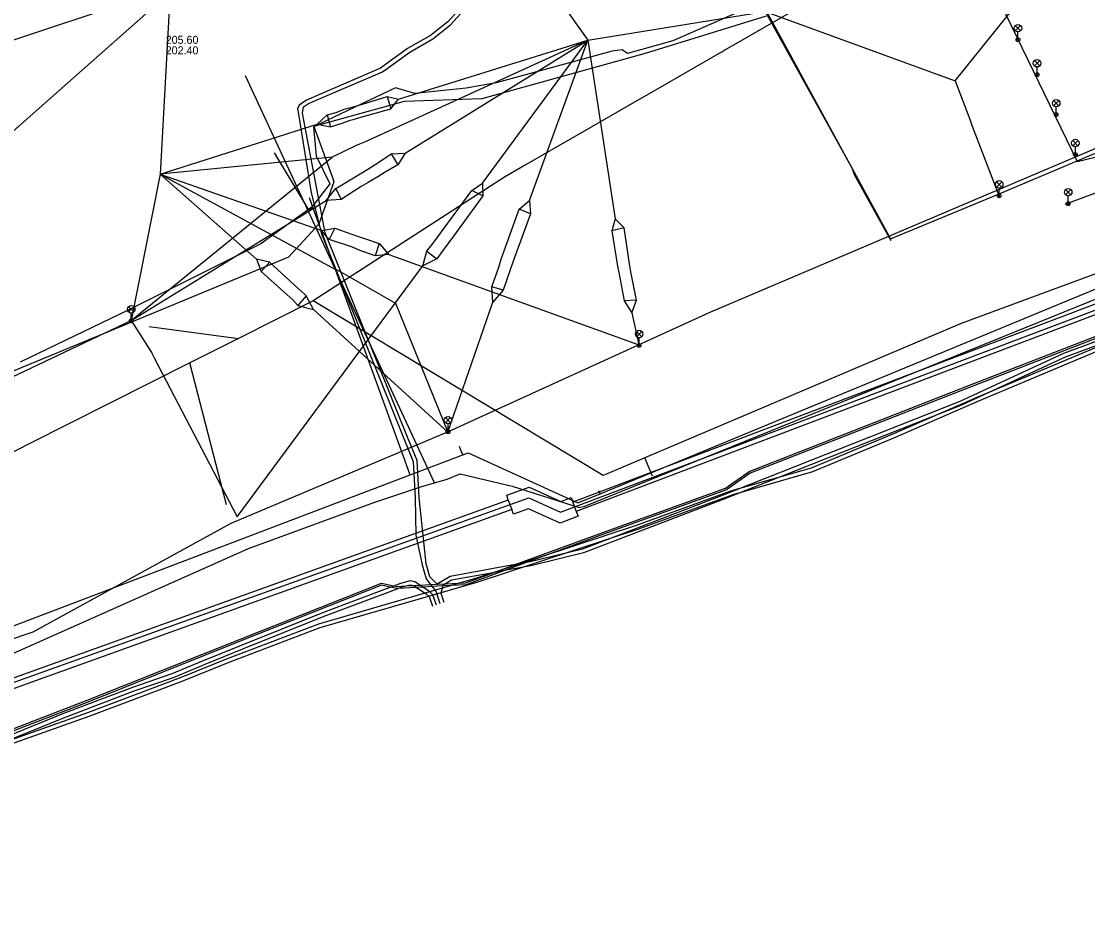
# Model space of a CAD drawing. Extents: x -596228 to -595156, y -1161235 to -1159373.
# Drawn here: x -595672.5 to -595565.9, y -1160372.3 to -1160281.7 of the extents above; entities that cross this region are included whole.
import ezdxf

# ---------------------------------------------------------------- set-up
doc = ezdxf.new("R2010")
doc.units = 0
for name, color, linetype in [('Vrstva 1', 7, 'Continuous'), ('Vrstva 10', 7, 'Continuous'), ('Vrstva 12', 7, 'Continuous'), ('Vrstva 14', 7, 'Continuous'), ('Vrstva 16', 7, 'Continuous'), ('Vrstva 33', 7, 'Continuous'), ('Vrstva 42', 7, 'Continuous'), ('Vrstva 44', 7, 'Continuous'), ('Vrstva 54', 7, 'Continuous'), ('Vrstva 55', 7, 'Continuous'), ('Vrstva 9', 7, 'Continuous')]:
    doc.layers.add(name, color=color, linetype=linetype)

msp = doc.modelspace()

# ---------------------------------------------------------------- linework, layer by layer
at = {"layer": 'Vrstva 1'}
for p, q in [((-595659.743, -1160312.174), (-595650.824, -1160313.363)), ((-595652.016, -1160330.002), (-595655.67, -1160315.804))]:
    msp.add_line(p, q, dxfattribs=at)
at = {"layer": 'Vrstva 10'}
for p, q in [((-595556.13, -1160306.5), (-595617.39, -1160329.73)), ((-595556.13, -1160306.5), (-595617.39, -1160329.73)), ((-595555.81, -1160307.45), (-595617.04, -1160330.67)), ((-595555.81, -1160307.45), (-595617.04, -1160330.67)), ((-595623.84, -1160329.51), (-595690.16, -1160353.38)), ((-595623.84, -1160329.51), (-595690.16, -1160353.38)), ((-595623.84, -1160329.51), (-595623.5, -1160330.45)), ((-595623.84, -1160329.51), (-595623.5, -1160330.45)), ((-595617.39, -1160329.73), (-595617.04, -1160330.67)), ((-595617.39, -1160329.73), (-595617.04, -1160330.67)), ((-595623.5, -1160330.45), (-595689.9, -1160354.35)), ((-595623.5, -1160330.45), (-595689.9, -1160354.35))]:
    msp.add_line(p, q, dxfattribs=at)
for points in [[(-595623.84, -1160329.51), (-595624, -1160329.04), (-595621.74, -1160328.23), (-595618.58, -1160329.65), (-595617.57, -1160329.26), (-595617.39, -1160329.73)], [(-595623.84, -1160329.51), (-595624, -1160329.04), (-595621.74, -1160328.23), (-595618.58, -1160329.65), (-595617.57, -1160329.26), (-595617.39, -1160329.73)], [(-595617.04, -1160330.67), (-595616.86, -1160331.13), (-595618.65, -1160331.81), (-595621.82, -1160330.38), (-595623.33, -1160330.92), (-595623.5, -1160330.45)], [(-595617.04, -1160330.67), (-595616.86, -1160331.13), (-595618.65, -1160331.81), (-595621.82, -1160330.38), (-595623.33, -1160330.92), (-595623.5, -1160330.45)]]:
    msp.add_lwpolyline(points, dxfattribs=at)
at = {"layer": 'Vrstva 12'}
msp.add_lwpolyline([(-595733.28, -1160359.44), (-595691.96, -1160354.4), (-595622.73, -1160329.64), (-595621.78, -1160329.3), (-595618.62, -1160330.73), (-595554.08, -1160306.33)], dxfattribs=at)
at = {"layer": 'Vrstva 14'}
for p, q in [((-595633.652, -1160327.007), (-595628.395, -1160325.007)), ((-595628.516, -1160324.69), (-595628.716, -1160324.165)), ((-595628.395, -1160325.007), (-595628.516, -1160324.69)), ((-595633.652, -1160327.007), (-595633.714, -1160326.844)), ((-595614.67, -1160328.883), (-595614.788, -1160328.598))]:
    msp.add_line(p, q, dxfattribs=at)
for points in [[(-595643.344, -1160300.351), (-595643.571, -1160300.434), (-595643.778, -1160300.509), (-595647.213, -1160294.815)], [(-595614.67, -1160328.883), (-595547.051, -1160300.94), (-595538.035, -1160297.214), (-595529.442, -1160294.26)], [(-595633.714, -1160326.844), (-595633.856, -1160326.471), (-595634.328, -1160325.169), (-595643.344, -1160300.351), (-595643.725, -1160299.302)], [(-595628.395, -1160325.007), (-595627.869, -1160324.806), (-595616.876, -1160329.795), (-595614.67, -1160328.883)], [(-595749.15, -1160356.25), (-595745.334, -1160357.016), (-595740.305, -1160357.959), (-595721.901, -1160355.127), (-595697.852, -1160351.426), (-595690.937, -1160348.796), (-595633.652, -1160327.007)]]:
    msp.add_lwpolyline(points, dxfattribs=at)
at = {"layer": 'Vrstva 16'}
msp.add_line((-595631.22, -1160327.8), (-595650.11, -1160287.1), dxfattribs=at)
msp.add_lwpolyline([(-595846.15, -1160336.98), (-595838.77, -1160338.11), (-595833.73, -1160339.33), (-595822.21, -1160341.41), (-595795.62, -1160345.96), (-595752.4, -1160353.65), (-595705.45, -1160352.2), (-595699.2, -1160353.46), (-595687.59, -1160351.18), (-595687.183, -1160350.999), (-595649.82, -1160334.37), (-595637.18, -1160329.71), (-595632.58, -1160328.19), (-595631.22, -1160327.8), (-595629.94, -1160327.43), (-595628.67, -1160326.89), (-595623.45, -1160328.11), (-595616.75, -1160330.26), (-595616.2, -1160330.11), (-595541.13, -1160299.69), (-595536.93, -1160298.59)], dxfattribs=at)
at = {"layer": 'Vrstva 33'}
for p, q in [((-595573.155, -1160282.085), (-595572.625, -1160282.615)), ((-595573.155, -1160282.615), (-595572.625, -1160282.085)), ((-595572.89, -1160283.5), (-595572.89, -1160282.725)), ((-595571.245, -1160285.585), (-595570.715, -1160286.115)), ((-595571.245, -1160286.115), (-595570.715, -1160285.585)), ((-595570.98, -1160287), (-595570.98, -1160286.225)), ((-595569.325, -1160289.575), (-595568.795, -1160290.105)), ((-595569.325, -1160290.105), (-595568.795, -1160289.575)), ((-595569.06, -1160290.99), (-595569.06, -1160290.215)), ((-595567.415, -1160293.565), (-595566.885, -1160294.095)), ((-595567.415, -1160294.095), (-595566.885, -1160293.565)), ((-595567.15, -1160294.98), (-595567.15, -1160294.205)), ((-595575.025, -1160297.695), (-595574.495, -1160298.225)), ((-595575.025, -1160298.225), (-595574.495, -1160297.695)), ((-595574.76, -1160299.11), (-595574.76, -1160298.335)), ((-595568.125, -1160298.475), (-595567.595, -1160299.005)), ((-595568.125, -1160299.005), (-595567.595, -1160298.475)), ((-595567.86, -1160299.89), (-595567.86, -1160299.115)), ((-595661.805, -1160310.185), (-595661.275, -1160310.715)), ((-595661.805, -1160310.715), (-595661.275, -1160310.185)), ((-595661.54, -1160311.6), (-595661.54, -1160310.825)), ((-595611.025, -1160312.655), (-595610.495, -1160313.185)), ((-595611.025, -1160313.185), (-595610.495, -1160312.655)), ((-595610.76, -1160314.07), (-595610.76, -1160313.295)), ((-595630.135, -1160321.265), (-595629.605, -1160321.795)), ((-595630.135, -1160321.795), (-595629.605, -1160321.265)), ((-595629.87, -1160322.68), (-595629.87, -1160321.905))]:
    msp.add_line(p, q, dxfattribs=at)
for centre, radius in [((-595572.89, -1160282.35), 0.375), ((-595572.89, -1160283.5), 0.19), ((-595572.89, -1160283.5), 0.05), ((-595570.98, -1160285.85), 0.375), ((-595570.98, -1160287), 0.19), ((-595570.98, -1160287), 0.05), ((-595569.06, -1160289.84), 0.375), ((-595569.06, -1160290.99), 0.19), ((-595569.06, -1160290.99), 0.05), ((-595567.15, -1160293.83), 0.375), ((-595567.15, -1160294.98), 0.19), ((-595567.15, -1160294.98), 0.05), ((-595574.76, -1160297.96), 0.375), ((-595567.86, -1160298.74), 0.375), ((-595574.76, -1160299.11), 0.19), ((-595574.76, -1160299.11), 0.05), ((-595567.86, -1160299.89), 0.19), ((-595567.86, -1160299.89), 0.05), ((-595661.54, -1160310.45), 0.375), ((-595661.54, -1160311.6), 0.19), ((-595661.54, -1160311.6), 0.05), ((-595610.76, -1160312.92), 0.375), ((-595610.76, -1160314.07), 0.19), ((-595610.76, -1160314.07), 0.05), ((-595629.87, -1160321.53), 0.375), ((-595629.87, -1160322.68), 0.19), ((-595629.87, -1160322.68), 0.05)]:
    msp.add_circle(centre, radius, dxfattribs=at)
at = {"layer": 'Vrstva 42'}
for points in [[(-595564.53, -1160268.19), (-595566.79, -1160270.52), (-595571.2, -1160272.79), (-595583.54, -1160277.43), (-595586.61, -1160277.56), (-595590.82, -1160278.37), (-595594.37, -1160278.59), (-595597.88, -1160279.42), (-595607.38, -1160283.62), (-595611.94, -1160284.88), (-595612.46, -1160284.51), (-595613.45, -1160284.64), (-595625.04, -1160287.81), (-595628.07, -1160288.33), (-595633.2, -1160288.88), (-595635.11, -1160288.31), (-595643.31, -1160292.2), (-595643.06, -1160295.12), (-595641.7, -1160297.92), (-595643.5, -1160300.23), (-595648.58, -1160303.89), (-595661.84, -1160310.55), (-595672.63, -1160315.73)], [(-595564.53, -1160268.19), (-595566.79, -1160270.52), (-595571.2, -1160272.79), (-595583.54, -1160277.43), (-595586.61, -1160277.56), (-595590.82, -1160278.37), (-595594.37, -1160278.59), (-595597.88, -1160279.42), (-595607.38, -1160283.62), (-595611.94, -1160284.88), (-595612.46, -1160284.51), (-595613.45, -1160284.64), (-595625.04, -1160287.81), (-595628.07, -1160288.33), (-595633.2, -1160288.88), (-595635.11, -1160288.31), (-595643.31, -1160292.2), (-595643.06, -1160295.12), (-595641.7, -1160297.92), (-595643.5, -1160300.23), (-595648.58, -1160303.89), (-595661.84, -1160310.55), (-595672.63, -1160315.73)], [(-595564.53, -1160268.19), (-595566.79, -1160270.52), (-595571.2, -1160272.79), (-595583.54, -1160277.43), (-595586.61, -1160277.56), (-595590.82, -1160278.37), (-595594.37, -1160278.59), (-595597.88, -1160279.42), (-595607.38, -1160283.62), (-595611.94, -1160284.88), (-595612.46, -1160284.51), (-595613.45, -1160284.64), (-595625.04, -1160287.81), (-595628.07, -1160288.33), (-595633.2, -1160288.88), (-595635.11, -1160288.31), (-595643.31, -1160292.2), (-595643.06, -1160295.12), (-595641.7, -1160297.92), (-595643.5, -1160300.23), (-595648.58, -1160303.89), (-595661.84, -1160310.55), (-595672.63, -1160315.73)], [(-595564.53, -1160268.19), (-595566.79, -1160270.52), (-595571.2, -1160272.79), (-595583.54, -1160277.43), (-595586.61, -1160277.56), (-595590.82, -1160278.37), (-595594.37, -1160278.59), (-595597.88, -1160279.42), (-595607.38, -1160283.62), (-595611.94, -1160284.88), (-595612.46, -1160284.51), (-595613.45, -1160284.64), (-595625.04, -1160287.81), (-595628.07, -1160288.33), (-595633.2, -1160288.88), (-595635.11, -1160288.31), (-595643.31, -1160292.2), (-595643.06, -1160295.12), (-595641.7, -1160297.92), (-595643.5, -1160300.23), (-595648.58, -1160303.89), (-595661.84, -1160310.55), (-595672.63, -1160315.73)], [(-595628.123, -1160279.792), (-595629.888, -1160281.721), (-595631.624, -1160283.069), (-595633.919, -1160284.394), (-595636.628, -1160286.352), (-595644.008, -1160289.527), (-595644.76, -1160290.027), (-595644.918, -1160290.395), (-595644.818, -1160290.936), (-595643.539, -1160298.801), (-595642.524, -1160302.908), (-595634.288, -1160323.372), (-595633.365, -1160325.656), (-595633.164, -1160329.297), (-595633.071, -1160333.02), (-595632.45, -1160335.99), (-595632.04, -1160337.396), (-595631.608, -1160337.969), (-595631.463, -1160338.162), (-595631.097, -1160338.647), (-595631.067, -1160338.697), (-595630.673, -1160339.855)], [(-595561.987, -1160312.519), (-595568.319, -1160314.864), (-595578.686, -1160319.652), (-595602.622, -1160329.131), (-595616.428, -1160334.42), (-595621.668, -1160335.701), (-595622.024, -1160335.765), (-595623.167, -1160335.973), (-595629.66, -1160337.15), (-595630.966, -1160337.929), (-595631.68, -1160337.204), (-595632.06, -1160335.902), (-595632.764, -1160329.273), (-595632.969, -1160325.568), (-595633.918, -1160323.222), (-595642.14, -1160302.788), (-595644.414, -1160290.839), (-595644.302, -1160290.222), (-595643.812, -1160289.877), (-595636.43, -1160286.702), (-595633.701, -1160284.73), (-595631.4, -1160283.401), (-595629.616, -1160282.015), (-595627.915, -1160280.15)], [(-595598.08, -1160280.55), (-595585.62, -1160303.42), (-595574.78, -1160298.9), (-595556.39, -1160291.15), (-595536.54, -1160296.17), (-595511.97, -1160292.34)], [(-595678.894, -1160354.516), (-595665.947, -1160349.527), (-595650.707, -1160343.437), (-595636.529, -1160337.816), (-595635.296, -1160338.081), (-595634.982, -1160338.149), (-595634.099, -1160338.102), (-595633.34, -1160338.061), (-595632.642, -1160338.024), (-595631.608, -1160337.969), (-595630.12, -1160337.889), (-595628.09, -1160337.781), (-595625.353, -1160336.776), (-595623.167, -1160335.973), (-595614.764, -1160332.886), (-595602.117, -1160328.311), (-595599.768, -1160326.651), (-595577.906, -1160318.107), (-595563.975, -1160312.716)], [(-595563.905, -1160312.904), (-595577.834, -1160318.293), (-595599.672, -1160326.829), (-595602.023, -1160328.489), (-595614.696, -1160333.074), (-595622.024, -1160335.765), (-595624.211, -1160336.569), (-595628.05, -1160337.979), (-595630.401, -1160338.105), (-595631.463, -1160338.162), (-595632.356, -1160338.21), (-595633.034, -1160338.246), (-595634.857, -1160338.343), (-595634.998, -1160338.351), (-595635.642, -1160338.212), (-595636.511, -1160338.024), (-595650.633, -1160343.623), (-595665.873, -1160349.713), (-595678.826, -1160354.704)], [(-595561.845, -1160312.893), (-595568.165, -1160315.234), (-595578.528, -1160320.02), (-595602.476, -1160329.503), (-595616.308, -1160334.802), (-595621.584, -1160336.093), (-595624.211, -1160336.569), (-595625.353, -1160336.776), (-595629.518, -1160337.53), (-595630.12, -1160337.889), (-595630.386, -1160338.048), (-595630.401, -1160338.105), (-595630.598, -1160338.837), (-595630.295, -1160339.726)], [(-595676.303, -1160354.082), (-595668.266, -1160350.83), (-595661.388, -1160348.207), (-595657.459, -1160346.867), (-595654.307, -1160345.565), (-595650.529, -1160344.009), (-595642.394, -1160340.755), (-595635.642, -1160338.212), (-595635.296, -1160338.081), (-595634.575, -1160337.81), (-595633.622, -1160337.568), (-595633.135, -1160337.704), (-595632.642, -1160338.024), (-595632.356, -1160338.21), (-595631.809, -1160338.565), (-595631.408, -1160338.939), (-595631.052, -1160339.985)], [(-595684.368, -1160360.824), (-595684.917, -1160360.681), (-595685.413, -1160360.091), (-595685.972, -1160358.576), (-595685.818, -1160358.132), (-595683.778, -1160357.346), (-595676.157, -1160354.454), (-595668.12, -1160351.202), (-595661.252, -1160348.583), (-595657.317, -1160347.241), (-595654.155, -1160345.935), (-595650.379, -1160344.379), (-595642.25, -1160341.127), (-595634.857, -1160338.343), (-595634.455, -1160338.192), (-595634.099, -1160338.102), (-595633.626, -1160337.982), (-595633.34, -1160338.061), (-595633.301, -1160338.072), (-595633.034, -1160338.246), (-595632.057, -1160338.881), (-595631.753, -1160339.163), (-595631.429, -1160340.113)]]:
    msp.add_lwpolyline(points, dxfattribs=at)
at = {"layer": 'Vrstva 44'}
for points in [[(-595717.364, -1160360.106), (-595716.77, -1160359.938), (-595712.271, -1160360.888), (-595708.136, -1160362.092), (-595704.554, -1160363.181), (-595701.491, -1160363.274), (-595693.888, -1160361.725), (-595687.262, -1160359.141), (-595675.243, -1160354.482), (-595665.747, -1160351.12), (-595656.455, -1160347.611), (-595651.761, -1160345.734), (-595642.65, -1160342.268), (-595626.862, -1160337.683), (-595610.795, -1160332.384), (-595601.354, -1160328.949), (-595593.41, -1160326.668), (-595585.132, -1160323.221), (-595576.808, -1160319.609), (-595564.888, -1160314.602), (-595558.278, -1160311.976), (-595541.589, -1160305.764), (-595540.697, -1160305.102), (-595540.254, -1160304.773)], [(-595717.89, -1160359.792), (-595716.784, -1160359.526), (-595712.174, -1160360.5), (-595708.022, -1160361.709), (-595704.489, -1160362.783), (-595701.525, -1160362.873), (-595694.001, -1160361.34), (-595687.407, -1160358.768), (-595675.382, -1160354.107), (-595665.884, -1160350.744), (-595656.6, -1160347.238), (-595651.906, -1160345.361), (-595642.777, -1160341.888), (-595626.98, -1160337.301), (-595610.926, -1160332.006), (-595601.478, -1160328.568), (-595593.543, -1160326.29), (-595585.289, -1160322.853), (-595576.965, -1160319.241), (-595565.039, -1160314.232)]]:
    msp.add_lwpolyline(points, dxfattribs=at)
at = {"layer": 'Vrstva 54'}
for p, q in [((-595627.289, -1160267.424), (-595615.875, -1160283.555)), ((-595579.158, -1160287.602), (-595564.055, -1160268.793)), ((-595681.72, -1160286.32), (-595657.64, -1160278.29)), ((-595657.64, -1160278.29), (-595658.64, -1160296.948)), ((-595615.875, -1160283.555), (-595598.145, -1160280.664)), ((-595598.145, -1160280.664), (-595579.158, -1160287.602)), ((-595635.949, -1160289.176), (-595635.569, -1160290.396)), ((-595641.944, -1160291.002), (-595641.632, -1160292.219)), ((-595661.531, -1160311.558), (-595641.459, -1160295.235)), ((-595635.536, -1160294.917), (-595634.873, -1160296.002)), ((-595658.64, -1160296.948), (-595661.531, -1160311.558)), ((-595641.096, -1160298.359), (-595640.553, -1160299.48)), ((-595626.4, -1160299.101), (-595627.503, -1160298.568)), ((-595621.626, -1160300.905), (-595622.759, -1160300.444)), ((-595641.17, -1160302.34), (-595641.752, -1160303.47)), ((-595612.27, -1160302.297), (-595613.504, -1160302.617)), ((-595636.755, -1160303.883), (-595637.151, -1160305.109)), ((-595631.973, -1160304.645), (-595630.981, -1160305.407)), ((-595647.73, -1160305.75), (-595648.548, -1160306.664)), ((-595644.045, -1160309.106), (-595644.878, -1160310.052)), ((-595624.348, -1160308.542), (-595625.493, -1160308.215)), ((-595611.008, -1160309.527), (-595612.247, -1160309.602))]:
    msp.add_line(p, q, dxfattribs=at)
for points in [[(-595598.145, -1160280.664), (-595589.47, -1160296.36), (-595589.253, -1160296.957), (-595585.589, -1160303.568)], [(-595661.531, -1160311.558), (-595642.046, -1160299.563), (-595641.096, -1160298.359), (-595638.498, -1160296.807), (-595637.879, -1160296.44), (-595637.508, -1160296.195), (-595636.887, -1160295.794), (-595635.536, -1160294.917), (-595634.153, -1160294.825), (-595615.875, -1160283.555)], [(-595658.64, -1160296.948), (-595642.959, -1160291.942), (-595641.944, -1160291.002), (-595641.066, -1160290.76), (-595640.254, -1160290.426), (-595639.597, -1160290.279), (-595638.848, -1160290.087), (-595635.949, -1160289.176), (-595634.835, -1160289.452), (-595615.875, -1160283.555)], [(-595615.875, -1160283.555), (-595638.223, -1160293.727), (-595639.036, -1160294.082), (-595641.459, -1160295.235), (-595658.64, -1160296.948)], [(-595650.954, -1160331.19), (-595632.393, -1160306.087), (-595631.973, -1160304.645), (-595631.144, -1160303.56), (-595630.633, -1160302.827), (-595627.503, -1160298.568), (-595626.406, -1160297.824), (-595615.875, -1160283.555)], [(-595629.876, -1160322.744), (-595625.378, -1160309.719), (-595625.493, -1160308.215), (-595624.778, -1160306.252), (-595624.542, -1160305.446), (-595622.759, -1160300.444), (-595621.726, -1160299.585), (-595615.875, -1160283.555)], [(-595615.875, -1160283.555), (-595613.16, -1160301.397), (-595613.504, -1160302.617), (-595612.909, -1160306.143), (-595612.757, -1160306.934), (-595612.247, -1160309.602), (-595611.482, -1160310.792), (-595610.777, -1160313.993)], [(-595579.158, -1160287.602), (-595577.662, -1160291.528), (-595577.45, -1160292.135), (-595574.784, -1160299.079)], [(-595642.959, -1160291.942), (-595641.632, -1160292.219), (-595640.455, -1160291.83), (-595639.635, -1160291.549), (-595639.367, -1160291.467), (-595638.581, -1160291.233), (-595635.569, -1160290.396), (-595634.835, -1160289.452)], [(-595634.153, -1160294.825), (-595634.873, -1160296.002), (-595636.167, -1160296.733), (-595636.873, -1160297.195), (-595637.86, -1160297.763), (-595638.547, -1160298.187), (-595640.553, -1160299.48), (-595642.046, -1160299.563)], [(-595658.64, -1160296.948), (-595642.508, -1160302.561), (-595641.17, -1160302.34), (-595638.906, -1160303.146), (-595638.107, -1160303.404), (-595636.755, -1160303.883), (-595635.781, -1160304.955), (-595610.777, -1160313.993)], [(-595658.64, -1160296.948), (-595641.48, -1160306.275), (-595640.733, -1160306.639), (-595635.131, -1160309.848), (-595629.876, -1160322.744)], [(-595629.876, -1160322.744), (-595643.306, -1160310.464), (-595644.045, -1160309.106), (-595644.249, -1160308.903), (-595644.847, -1160308.382), (-595647.73, -1160305.75), (-595649.017, -1160305.438), (-595658.64, -1160296.948)], [(-595626.406, -1160297.824), (-595626.4, -1160299.101), (-595629.597, -1160303.515), (-595630.131, -1160304.204), (-595630.981, -1160305.407), (-595632.393, -1160306.087)], [(-595621.726, -1160299.585), (-595621.626, -1160300.905), (-595623.343, -1160305.635), (-595623.66, -1160306.496), (-595624.348, -1160308.542), (-595625.378, -1160309.719)], [(-595611.482, -1160310.792), (-595611.008, -1160309.527), (-595611.587, -1160306.713), (-595611.713, -1160305.903), (-595612.27, -1160302.297), (-595613.16, -1160301.397)], [(-595635.781, -1160304.955), (-595637.151, -1160305.109), (-595638.748, -1160304.523), (-595639.429, -1160304.252), (-595641.752, -1160303.47), (-595642.508, -1160302.561)], [(-595649.017, -1160305.438), (-595648.548, -1160306.664), (-595645.976, -1160308.97), (-595645.398, -1160309.517), (-595644.878, -1160310.052), (-595643.306, -1160310.464)], [(-595701.714, -1160326.591), (-595683.484, -1160321.975), (-595661.488, -1160311.527)], [(-595661.531, -1160311.558), (-595659.52, -1160314.781), (-595659.215, -1160315.366), (-595650.954, -1160331.19)]]:
    msp.add_lwpolyline(points, dxfattribs=at)
at = {"layer": 'Vrstva 55'}
for points in [[(-595585.542, -1160267.498), (-595581.992, -1160278.439), (-595576.288, -1160276.402), (-595566.976, -1160295.667), (-595564.066, -1160294.968), (-595562.262, -1160297.762), (-595568.198, -1160299.974)], [(-595598.074, -1160281.158), (-595610.16, -1160284.89), (-595626.48, -1160289.4), (-595634.26, -1160289.66), (-595643.29, -1160292.17), (-595641.433, -1160297.27)], [(-595549.591, -1160289.23), (-595553.77, -1160289.9), (-595560.32, -1160292.33), (-595603.64, -1160310.74), (-595629.87, -1160322.68), (-595651.581, -1160331.852), (-595671.361, -1160342.72), (-595690.48, -1160349.14), (-595700.77, -1160351.15), (-595713.32, -1160352.4), (-595737.16, -1160354.91), (-595741.43, -1160359.43), (-595737.66, -1160362.94), (-595735.46, -1160369.37), (-595740.08, -1160372.02)], [(-595641.433, -1160297.27), (-595641.28, -1160297.69), (-595642.79, -1160301.95), (-595645.8, -1160305.22), (-595683.45, -1160320.78), (-595697.51, -1160325.55), (-595715.58, -1160330.31), (-595736.829, -1160332.482), (-595742.491, -1160332.8), (-595749.21, -1160333.08), (-595745.95, -1160355.16), (-595741.43, -1160359.18), (-595737.41, -1160363.19), (-595735.15, -1160369.47), (-595738.78, -1160371.82), (-595739.832, -1160372.258)]]:
    msp.add_lwpolyline(points, dxfattribs=at)
at = {"layer": 'Vrstva 9'}
for p, q in [((-595546.519, -1160300.041), (-595578.568, -1160311.866)), ((-595614.36, -1160327.06), (-595643.35, -1160309.6)), ((-595671.75, -1160323.9), (-595708.84, -1160343.06)), ((-595609.423, -1160327.137), (-595610.205, -1160325.296))]:
    msp.add_line(p, q, dxfattribs=at)
for points in [[(-595587.06, -1160275.84), (-595594.009, -1160279.841), (-595594.35, -1160280.037), (-595602.255, -1160284.589), (-595602.442, -1160284.697), (-595602.664, -1160284.825), (-595609.126, -1160288.545), (-595611.858, -1160290.118), (-595615.554, -1160292.246), (-595622.23, -1160296.09), (-595624.21, -1160297.23)], [(-595658.76, -1160279.74), (-595660.079, -1160280.905), (-595696.26, -1160312.9)], [(-595624.21, -1160297.23), (-595627.107, -1160299.102), (-595643.35, -1160309.6)], [(-595643.35, -1160309.6), (-595650.824, -1160313.363), (-595655.67, -1160315.804), (-595671.75, -1160323.9)], [(-595578.568, -1160311.866), (-595610.205, -1160325.296), (-595614.36, -1160327.06)]]:
    msp.add_lwpolyline(points, dxfattribs=at)

# ---------------------------------------------------------------- texts
at = {"layer": 'Vrstva 12'}
for s, p in [('205.60', (-595658.092, -1160283.911)), ('202.40', (-595658.092, -1160284.961))]:
    msp.add_text(s, height=0.8, dxfattribs=at).set_placement(p)

doc.saveas('drawing.dxf')
